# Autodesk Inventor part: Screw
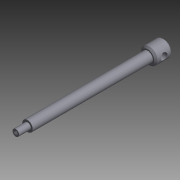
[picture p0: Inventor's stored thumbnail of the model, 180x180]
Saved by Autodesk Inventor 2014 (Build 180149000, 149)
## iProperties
Shininess: 12.0
Length Units: 11272
Angle Units: 11279
Time Units: 11290
Mass Units: 11283
Length Display Precision: 2
Angle Display Precision: 1
Compacted: True
Created: 1999-05
Part Number: Screw
Document SubType Name: Modeling
Designer: Administrator
Density: 7.86 g/cm^3
Material: Steel, Mild
Mass: 93.6133 g
Surface Area: 51.8791 cm^2
Volume: 11.9101 cm^3
Appearance: Metal - Steel 2
Density: 8.94
Volumn: 11.91003151861203
Area: 51.879342766234146
PropertySet Name: Model Information
Control State: 0
Master: False
Checked Out: False
Author: Administrator
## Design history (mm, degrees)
node "y-z Plane"
  node "x-z Plane"
  node "x-y Plane"
node "Extrusion1" dims "d1" = 15.748, "d2" = 0
  sketch "Sketch1"
    geometry: C1 r 7.874 at (0, 0); 1 further point
    constraints: 1 centre point, 1 coincident
    dimensions: "d0" = 15.748 diameter of C1
node "Extrusion2" dims "d3" = 114.3, "d4" = 0
  sketch "Sketch2"
    geometry: C1 r 7.874 at (0, 0) reference; C2 r 5.044 at (0, 0)
    constraints: 1 centre point
node "Extrusion3" dims "d6" = 11.176, "d7" = 0
  sketch "Sketch3"
    geometry: C1 r 5.044 at (0, 0) reference; C2 r 3.175 at (0, 0)
    constraints: 1 centre point
    dimensions: "d5" = 6.35 diameter of C2
node "Hole1" dims "d8" = 3.9624, "d9" = 9.525, "d10" = 6.35, "d11" = 60 deg, "d12" = 3.175, "d13" = 118 deg, "d29" = 19.05
  sketch "Sketch4"
    geometry: C1 r 3.175 at (0, 0) reference
workplane "Work Plane1"
  workaxis "Work Axis1"
workplane "Work Plane2"
workplane "Work Plane3"
node "Hole2" dims "d20" = 6.35, "d21" = 9.525, "d22" = 6.35, "d23" = 60 deg, "d24" = 19.05, "d25" = 118 deg
  sketch "Sketch5"
    geometry: L1 (0, 3.15)-(0, -18.898) reference; L2 (-11.024, 0)-(11.024, 0) reference; 1 further point
    constraints: 1 midpoint
    dimensions: "d28" = 7.874 distance from line of point (0, -7.874) L2
node "Chamfer1" dims "d26" = 1.5875, "d27" = 1.5875, "d30" = 45 deg
workaxis "Work Axis2"
workaxis "Work Axis3"
body "Solid1"
other parameters: "d14" = 45 deg, "d16" = 0, "d17" = 7.874
